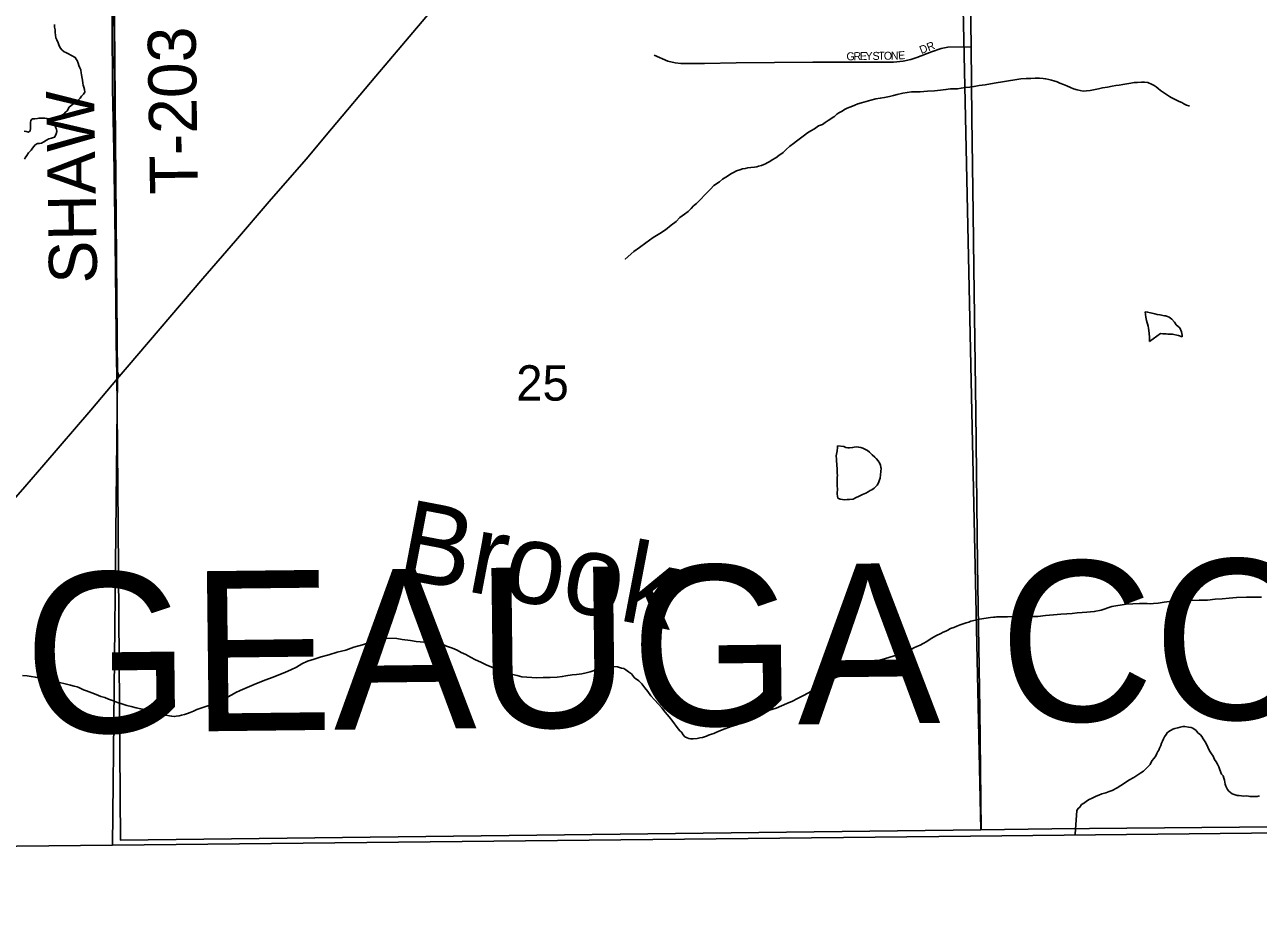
# Model space of a CAD drawing. Extents: x -10.1 to 68, y -9.5 to 29.2.
# Drawn here: x 6.404 to 7.864, y 16.795 to 17.837 of the extents above; entities that cross this region are included whole.
import ezdxf

# ---------------------------------------------------------------- set-up
doc = ezdxf.new("R2010")
doc.units = 0
for name, color, linetype in [('GM_X_Adjacent_County', 7, 'Continuous'), ('GM_X_Adjacent_County_Text', 7, 'Continuous'), ('GM_X_County_Road', 7, 'Continuous'), ('GM_X_Minor_Lake', 7, 'Continuous'), ('GM_X_Minor_River', 7, 'Continuous'), ('GM_X_Minor_River_Text', 7, 'Continuous'), ('GM_X_Section', 7, 'Continuous'), ('GM_X_Section_Text', 7, 'Continuous'), ('GM_X_Township', 7, 'Continuous'), ('GM_X_Township_Road', 7, 'Continuous'), ('GM_X_Township_Road_Text', 7, 'Continuous'), ('GM_X_Township_Subdivision', 7, 'Continuous'), ('GM_X_Township_Subdivision_Text', 7, 'Continuous')]:
    doc.layers.add(name, color=color, linetype=linetype)

msp = doc.modelspace()

# ---------------------------------------------------------------- linework, layer by layer
at = {"layer": 'GM_X_Adjacent_County'}
msp.add_lwpolyline([(8.9, 16.8967), (8.5023, 16.8904), (7.9665, 16.8821), (7.5233, 16.8774), (6.5083, 16.8667), (6.2435, 16.8638), (4.8206, 16.8372), (4.1632, 16.8285), (3.6875, 16.8223), (2.8045, 16.808), (2.1, 16.7954)], dxfattribs=at)
at = {"layer": 'GM_X_County_Road'}
msp.add_lwpolyline([(7.495, 19.6038), (7.4962, 19.5624), (7.4978, 19.473), (7.501, 19.2631), (7.5047, 19.0477), (7.5089, 18.8338), (7.5108, 18.7383), (7.5113, 18.6856), (7.513, 18.6303), (7.5141, 18.5902), (7.5161, 18.4613), (7.5177, 18.3096), (7.5197, 18.1709), (7.5217, 17.9835), (7.5233, 17.8668), (7.524, 17.8111), (7.5251, 17.7267), (7.5267, 17.614), (7.5273, 17.5492), (7.5298, 17.379), (7.5318, 17.1984), (7.5343, 17.0271), (7.5359, 16.8846)], dxfattribs=at)
at = {"layer": 'GM_X_Minor_Lake'}
for points in [[(6.4042, 17.6779), (6.4049, 17.6798), (6.4068, 17.6825), (6.409, 17.6856), (6.4119, 17.6887), (6.4138, 17.6911), (6.4153, 17.693), (6.4168, 17.6949), (6.4194, 17.6965), (6.422, 17.6966), (6.4243, 17.697), (6.4269, 17.6986), (6.4303, 17.7006), (6.4329, 17.7022), (6.436, 17.703), (6.4398, 17.7042), (6.4408, 17.7061), (6.4416, 17.7081), (6.4423, 17.7107), (6.4422, 17.7134), (6.4414, 17.7153), (6.4406, 17.7175), (6.4394, 17.7202), (6.4374, 17.7232), (6.4355, 17.7243), (6.4328, 17.7254), (6.4305, 17.7261), (6.4282, 17.7264), (6.4255, 17.7267), (6.4236, 17.7267), (6.4214, 17.7266), (6.4195, 17.7262), (6.4164, 17.7257), (6.4134, 17.7257), (6.4115, 17.7237), (6.4112, 17.7214), (6.4113, 17.7188), (6.4113, 17.7165), (6.4114, 17.7142), (6.4107, 17.7115), (6.4088, 17.71), (6.4061, 17.7107), (6.4038, 17.711)], [(7.7529, 17.4928), (7.7474, 17.494), (7.7443, 17.4943), (7.7413, 17.495), (7.7382, 17.4957), (7.7363, 17.4964), (7.7328, 17.4971), (7.7302, 17.4974), (7.7306, 17.4943), (7.7307, 17.4913), (7.7311, 17.489), (7.7315, 17.4871), (7.7336, 17.4807), (7.734, 17.4781), (7.7345, 17.4754), (7.7349, 17.472), (7.735, 17.4674), (7.7351, 17.4625)], [(7.7351, 17.4625), (7.7482, 17.4719), (7.7509, 17.4716), (7.7547, 17.4713), (7.757, 17.471), (7.7597, 17.471), (7.762, 17.4711), (7.7696, 17.4694), (7.7738, 17.4679), (7.7738, 17.4698), (7.7729, 17.474), (7.7709, 17.4785), (7.769, 17.48), (7.7667, 17.4822), (7.7647, 17.4852), (7.7616, 17.4886), (7.7585, 17.4912), (7.7565, 17.4919), (7.7539, 17.4926), (7.7529, 17.4928)], [(7.3659, 17.3388), (7.3659, 17.3369), (7.3656, 17.3331), (7.3646, 17.3273), (7.3647, 17.3232), (7.3653, 17.3148), (7.3657, 17.3129), (7.3657, 17.3106), (7.3658, 17.3083), (7.3658, 17.3064), (7.3659, 17.3042), (7.3656, 17.3015), (7.3656, 17.2984), (7.3657, 17.2962), (7.3657, 17.2943), (7.3658, 17.2908), (7.3659, 17.2886), (7.3659, 17.2863), (7.3656, 17.2844), (7.3656, 17.2817), (7.3661, 17.2794), (7.3665, 17.2772), (7.3692, 17.2757), (7.3719, 17.2754), (7.3745, 17.2751), (7.3776, 17.2755), (7.3802, 17.2756), (7.3844, 17.276), (7.3874, 17.2773), (7.3916, 17.2793), (7.3957, 17.2812), (7.3995, 17.2829), (7.4025, 17.2844), (7.4047, 17.286), (7.4066, 17.2868), (7.4096, 17.2888), (7.413, 17.2923), (7.4144, 17.295), (7.4158, 17.2988), (7.4166, 17.3007), (7.4175, 17.3127)], [(7.4175, 17.3127), (7.4174, 17.3133), (7.417, 17.316), (7.4162, 17.3182), (7.4142, 17.3212), (7.4119, 17.3239), (7.4103, 17.3257), (7.4072, 17.3283), (7.4037, 17.3313), (7.4014, 17.3335), (7.3983, 17.335), (7.396, 17.3361), (7.3937, 17.3368), (7.391, 17.3375), (7.3883, 17.3378), (7.3857, 17.3373), (7.3838, 17.3369), (7.3804, 17.3365), (7.3785, 17.3364), (7.3758, 17.3371), (7.3735, 17.3382), (7.3659, 17.3388)]]:
    msp.add_lwpolyline(points, dxfattribs=at)
at = {"layer": 'GM_X_Minor_River'}
for points in [[(6.4374, 17.7232), (6.4509, 17.7315), (6.4528, 17.7338), (6.4546, 17.7354), (6.4572, 17.7396), (6.4594, 17.7416), (6.4624, 17.7439), (6.4643, 17.7455), (6.4669, 17.7471), (6.4699, 17.7502), (6.4717, 17.7525), (6.474, 17.7548), (6.4754, 17.7572), (6.475, 17.7606), (6.4742, 17.7632), (6.4737, 17.7655), (6.4733, 17.7681), (6.4728, 17.7716), (6.472, 17.7753), (6.4715, 17.778), (6.4711, 17.7799), (6.4707, 17.7837), (6.4695, 17.7859), (6.4686, 17.789), (6.4678, 17.7916), (6.4666, 17.7946), (6.4654, 17.7965), (6.4642, 17.7984), (6.4554, 17.8031), (6.4531, 17.8042), (6.4511, 17.8049), (6.4484, 17.8075), (6.4469, 17.8094), (6.4453, 17.812), (6.444, 17.8158), (6.4424, 17.8192), (6.4413, 17.8214), (6.4408, 17.8249), (6.4403, 17.8279), (6.4403, 17.8309), (6.4398, 17.834), (6.4397, 17.8374)], [(7.115, 17.5599), (7.1251, 17.5688), (7.115, 17.5599), (7.1251, 17.5688), (7.1318, 17.5736), (7.1393, 17.5791), (7.1479, 17.5853), (7.1558, 17.5901), (7.1625, 17.5944), (7.1693, 17.5999), (7.1752, 17.6042), (7.1793, 17.6089), (7.1849, 17.6128), (7.1894, 17.616), (7.1928, 17.6195), (7.1957, 17.623), (7.1991, 17.6257), (7.2017, 17.628), (7.2047, 17.6312), (7.2084, 17.635), (7.2121, 17.6389), (7.2158, 17.6424), (7.2199, 17.6467), (7.2263, 17.6514), (7.23, 17.6542), (7.2338, 17.6569), (7.2372, 17.6589), (7.2398, 17.6605), (7.2428, 17.6621), (7.2465, 17.6641), (7.2503, 17.6653), (7.2537, 17.6665), (7.2568, 17.667), (7.2598, 17.6678), (7.2636, 17.6683), (7.2678, 17.6684), (7.2704, 17.6688), (7.2727, 17.6696), (7.2761, 17.6705), (7.2787, 17.6717), (7.281, 17.6725), (7.2829, 17.6737), (7.2859, 17.6752), (7.2889, 17.6772), (7.293, 17.6796), (7.2967, 17.6823), (7.3016, 17.6859), (7.3053, 17.6894), (7.3098, 17.6933), (7.3139, 17.6964), (7.3177, 17.6992), (7.327, 17.7066), (7.3304, 17.709), (7.3345, 17.7114), (7.339, 17.7141), (7.3435, 17.7173), (7.3484, 17.7189), (7.3514, 17.7213), (7.3548, 17.7236), (7.3581, 17.7256), (7.3608, 17.7276), (7.3626, 17.7284), (7.3653, 17.7311), (7.3675, 17.7327), (7.3698, 17.7339), (7.3716, 17.735), (7.3743, 17.7366), (7.3776, 17.7382), (7.3807, 17.7394), (7.3837, 17.7406), (7.3867, 17.7419), (7.3901, 17.7434), (7.3946, 17.7447), (7.3999, 17.7463), (7.4056, 17.748), (7.4113, 17.7493), (7.4166, 17.7501), (7.4215, 17.751), (7.4275, 17.7523), (7.4321, 17.7535), (7.4366, 17.7544), (7.4434, 17.7561), (7.4537, 17.7575), (7.464, 17.7577), (7.4727, 17.7583), (7.4807, 17.7588), (7.4879, 17.7598), (7.4943, 17.7603), (7.4996, 17.7612), (7.5042, 17.7613), (7.508, 17.7614), (7.5125, 17.7622), (7.5175, 17.7627), (7.5224, 17.7632), (7.5277, 17.7641), (7.5338, 17.765), (7.5406, 17.7659), (7.5471, 17.7672), (7.5539, 17.7685), (7.5611, 17.7694), (7.5831, 17.773)], [(7.5831, 17.773), (7.5892, 17.7735), (7.5949, 17.7736), (7.5998, 17.7737), (7.6051, 17.7738), (7.6093, 17.7736), (7.6124, 17.7729), (7.6162, 17.7722), (7.6193, 17.7715), (7.6219, 17.7708), (7.6258, 17.7694), (7.6292, 17.7679), (7.6335, 17.7665), (7.6373, 17.7647), (7.6415, 17.7629), (7.6454, 17.7611), (7.6496, 17.76), (7.653, 17.7593), (7.6565, 17.7586), (7.6606, 17.7587), (7.6648, 17.7592), (7.669, 17.7601), (7.6747, 17.7613), (7.6796, 17.7626), (7.6853, 17.7631), (7.691, 17.7644), (7.6955, 17.7652), (7.6993, 17.7657), (7.7035, 17.7662), (7.7084, 17.7671), (7.7129, 17.7679), (7.7171, 17.7688), (7.7209, 17.7689), (7.7255, 17.7693), (7.7293, 17.7691), (7.7331, 17.7688), (7.7385, 17.7662), (7.7408, 17.7651), (7.7431, 17.7637), (7.7454, 17.7618), (7.7481, 17.7592), (7.7516, 17.757), (7.7539, 17.7552), (7.7566, 17.7537), (7.759, 17.7522), (7.7609, 17.7511), (7.7701, 17.7464), (7.7736, 17.7449), (7.7759, 17.7435), (7.779, 17.742), (7.7817, 17.7413), (7.7824, 17.741)], [(7.4562, 17.1), (7.4599, 17.1016), (7.4637, 17.1032), (7.4675, 17.1052), (7.4716, 17.1076), (7.4757, 17.1103), (7.4795, 17.1127), (7.4832, 17.1147), (7.4881, 17.1171), (7.4911, 17.1187), (7.4941, 17.1199), (7.4964, 17.1211), (7.4998, 17.1227), (7.5036, 17.1239), (7.5073, 17.1255), (7.5111, 17.1271), (7.5149, 17.1283), (7.5183, 17.1295), (7.5213, 17.1304), (7.5239, 17.1316), (7.5292, 17.1328), (7.5341, 17.1341), (7.547, 17.1359), (7.5505, 17.1364), (7.5524, 17.1364), (7.5543, 17.1365), (7.5569, 17.1365), (7.5611, 17.1366), (7.5672, 17.1368), (7.5767, 17.137), (7.5851, 17.1368), (7.5942, 17.137), (7.6029, 17.1372), (7.6121, 17.1382), (7.6215, 17.1391), (7.6303, 17.1397), (7.6375, 17.1403), (7.6436, 17.1408), (7.6496, 17.1413), (7.6553, 17.1418), (7.661, 17.1423), (7.6698, 17.1429), (7.6781, 17.1446), (7.6906, 17.1491), (7.7076, 17.1517), (7.7232, 17.1525), (7.7323, 17.1523), (7.7358, 17.152), (7.74, 17.1525), (7.7453, 17.153), (7.7525, 17.1539), (7.7616, 17.1553), (7.7726, 17.1559), (7.7836, 17.1561), (7.7939, 17.1564), (7.8038, 17.1566), (7.8129, 17.1576), (7.8212, 17.1581), (7.8296, 17.1587), (7.838, 17.1597), (7.8501, 17.1599), (7.8589, 17.1601), (7.8676, 17.1599)], [(6.4121, 17.0662), (6.4171, 17.0652), (6.4224, 17.0642), (6.4308, 17.0629), (6.4381, 17.0607), (6.4454, 17.059), (6.4523, 17.0573), (6.4584, 17.0559), (6.463, 17.0545), (6.4664, 17.0538), (6.4683, 17.0531), (6.4707, 17.052), (6.4741, 17.0505), (6.4776, 17.0491), (6.4837, 17.0469), (6.4891, 17.0448), (6.4945, 17.0426), (6.4994, 17.0412), (6.5037, 17.0394), (6.5083, 17.0376), (6.514, 17.0355), (6.5194, 17.0337), (6.5251, 17.0319), (6.5305, 17.0305), (6.5362, 17.0291), (6.5416, 17.0277), (6.5492, 17.0264), (6.5661, 17.0218), (6.5714, 17.0204), (6.5756, 17.0197), (6.5783, 17.019), (6.5814, 17.0187), (6.5836, 17.0192), (6.5871, 17.0196), (6.5901, 17.0205), (6.5935, 17.0213), (6.5969, 17.0225), (6.6003, 17.0237), (6.6041, 17.0253), (6.6082, 17.027), (6.6127, 17.0286), (6.6176, 17.0302), (6.6222, 17.0318), (6.6267, 17.0335), (6.632, 17.0366), (6.6395, 17.0391), (6.6444, 17.0415), (6.6493, 17.0443), (6.6542, 17.047), (6.6594, 17.0494), (6.6647, 17.0518), (6.6704, 17.0543), (6.676, 17.0567), (6.6824, 17.0595), (6.6896, 17.0623), (6.6971, 17.0648), (6.7062, 17.0684), (6.713, 17.0712), (6.7194, 17.074), (6.7258, 17.0772), (6.7321, 17.0812), (6.7389, 17.0844), (6.7469, 17.0868), (6.7552, 17.0893), (6.7642, 17.0918), (6.7741, 17.0947), (6.7843, 17.0972), (6.7937, 17.1008), (6.8039, 17.1034), (6.81, 17.1054), (6.8149, 17.107), (6.819, 17.1086), (6.8236, 17.1095), (6.8277, 17.1107), (6.8315, 17.1116), (6.8445, 17.1111), (6.851, 17.1098), (6.8609, 17.1085), (6.8674, 17.1075), (6.8723, 17.1072), (6.8761, 17.1069), (6.8788, 17.107), (6.8811, 17.107), (6.8834, 17.1071), (6.886, 17.1068), (6.8902, 17.1065), (6.894, 17.1058), (6.8983, 17.1044), (6.9033, 17.1018), (6.9105, 17.0997), (6.9159, 17.0972), (6.9209, 17.0946), (6.9263, 17.0921), (6.9317, 17.0888), (6.9379, 17.0859), (6.944, 17.083), (6.9502, 17.0801), (6.9571, 17.0772), (6.9636, 17.0743), (6.9698, 17.0725), (6.9767, 17.0704)], [(6.9767, 17.0704), (6.9816, 17.0686), (6.987, 17.0672), (6.9927, 17.0658), (6.9985, 17.0652), (7.0042, 17.0649), (7.0103, 17.0647), (7.0179, 17.0649), (7.0262, 17.0651), (7.0342, 17.0652), (7.0403, 17.0661), (7.0448, 17.067), (7.0521, 17.0679), (7.0574, 17.0684), (7.0634, 17.0693), (7.0687, 17.0706), (7.0733, 17.0718), (7.0771, 17.0727), (7.0808, 17.0739), (7.0839, 17.0747), (7.0861, 17.0756), (7.0884, 17.076), (7.0907, 17.0768), (7.0941, 17.0776), (7.0971, 17.0781), (7.1059, 17.0775), (7.1082, 17.0768), (7.1105, 17.0761), (7.1131, 17.0754), (7.1158, 17.074), (7.1189, 17.0717), (7.1224, 17.0692), (7.1259, 17.0647), (7.131, 17.061), (7.1345, 17.0573), (7.138, 17.0528), (7.1415, 17.0483), (7.1451, 17.0434), (7.1494, 17.0386), (7.1541, 17.0333), (7.1583, 17.0289), (7.1623, 17.024), (7.167, 17.0184), (7.1713, 17.0128), (7.1764, 17.0057), (7.1795, 17.002), (7.1814, 17.0001), (7.1834, 16.9971), (7.1854, 16.9949), (7.1881, 16.9934), (7.19, 16.9927), (7.1923, 16.9924), (7.1953, 16.9924), (7.1999, 16.9929), (7.2033, 16.9934), (7.2063, 16.9938), (7.2086, 16.9946), (7.2109, 16.9955), (7.2135, 16.9967), (7.2169, 16.9979), (7.2199, 16.9987), (7.2222, 16.9999), (7.2248, 17.0011), (7.2278, 17.0023), (7.2327, 17.0043), (7.2369, 17.0056), (7.2414, 17.0072), (7.2456, 17.0084), (7.249, 17.0096), (7.2535, 17.0113), (7.258, 17.0133), (7.2629, 17.0157), (7.2795, 17.0229), (7.2855, 17.0261), (7.2934, 17.0285), (7.2998, 17.0313), (7.3062, 17.0342), (7.3126, 17.037), (7.3187, 17.0401), (7.325, 17.0433), (7.3318, 17.0469), (7.3382, 17.0509), (7.3446, 17.0544), (7.3513, 17.0588), (7.3585, 17.0624), (7.3668, 17.066), (7.3724, 17.0684), (7.3777, 17.0708), (7.383, 17.0728), (7.3883, 17.0748), (7.3935, 17.0769), (7.3996, 17.0789), (7.406, 17.0813), (7.4135, 17.0845), (7.423, 17.0874), (7.432, 17.0903), (7.4396, 17.0927), (7.4464, 17.0944), (7.4494, 17.096), (7.4524, 17.0976), (7.4562, 17.1)], [(6.4018, 17.0671), (6.4075, 17.0669), (6.4121, 17.0662)], [(7.6472, 16.8798), (7.6493, 16.9076), (7.6508, 16.91), (7.6526, 16.9115), (7.6548, 16.9146), (7.6582, 16.9166), (7.6608, 16.9186), (7.6638, 16.9205), (7.6672, 16.9221), (7.6695, 16.9233), (7.6721, 16.9245), (7.6751, 16.9257), (7.6789, 16.9273), (7.6834, 16.9286), (7.6876, 16.9302), (7.691, 16.9314), (7.697, 16.9346), (7.7011, 16.937), (7.7056, 16.9401), (7.7109, 16.9433), (7.7165, 16.9468), (7.7214, 16.9496), (7.7251, 16.952), (7.7281, 16.9543), (7.7311, 16.9571), (7.7337, 16.9598), (7.7359, 16.9621), (7.7381, 16.9664), (7.7407, 16.9695), (7.7426, 16.9722), (7.744, 16.9749), (7.7451, 16.9772), (7.7462, 16.9791), (7.7469, 16.9814), (7.7484, 16.9845), (7.7494, 16.9872), (7.7505, 16.9895), (7.7516, 16.9922), (7.7531, 16.9949), (7.7549, 16.9976), (7.756, 16.9995), (7.7579, 17.0011), (7.7628, 17.0038), (7.765, 17.0046), (7.7688, 17.0055), (7.7715, 17.0063), (7.7745, 17.0068), (7.7771, 17.0068), (7.7813, 17.0062), (7.7844, 17.0058), (7.7863, 17.0051), (7.7902, 17.0022), (7.7925, 16.9996), (7.7953, 16.997), (7.7972, 16.9951), (7.7988, 16.9925), (7.8011, 16.9887), (7.8027, 16.9861), (7.8043, 16.9827), (7.8063, 16.9782), (7.8087, 16.9748), (7.8103, 16.9718), (7.8119, 16.968), (7.8139, 16.965), (7.8155, 16.9624), (7.817, 16.9594), (7.8183, 16.9556), (7.8203, 16.9507), (7.8222, 16.9485), (7.8231, 16.9458), (7.8239, 16.9436), (7.8243, 16.9413), (7.8247, 16.9387), (7.8256, 16.9364), (7.8275, 16.9326), (7.8291, 16.9304), (7.8311, 16.9289), (7.833, 16.9274), (7.8364, 16.926), (7.8387, 16.9253), (7.8414, 16.9253), (7.8441, 16.925), (7.8468, 16.9247), (7.8494, 16.9248), (7.8521, 16.9244), (7.854, 16.9241), (7.8567, 16.9242), (7.8589, 16.9242), (7.8627, 16.9243), (7.8654, 16.9251)]]:
    msp.add_lwpolyline(points, dxfattribs=at)
at = {"layer": 'GM_X_Section'}
for points in [[(8.4834, 18.0059), (8.5076, 16.8938), (7.6195, 16.8859), (7.5357, 16.8848), (7.5119, 17.9844)], [(7.5119, 17.9844), (7.5357, 16.8848), (6.5178, 16.8724), (6.515, 17.2445), (6.5119, 17.6092), (6.5089, 17.9612)]]:
    msp.add_lwpolyline(points, close=True, dxfattribs=at)
at = {"layer": 'GM_X_Township'}
msp.add_lwpolyline([(6.49, 20.9), (6.4976, 19.3842), (6.5141, 17.4202), (6.5083, 16.8667), (7.5233, 16.8774), (7.9665, 16.8821), (8.5023, 16.8904), (8.9, 16.8967)], dxfattribs=at)
at = {"layer": 'GM_X_Township_Road'}
for points in [[(6.516, 17.421), (6.514, 17.4263), (6.5131, 17.4329), (6.5113, 17.5817), (6.5097, 17.6881), (6.5081, 17.7615), (6.5079, 17.838), (6.507, 17.9485), (6.5041, 18.126), (6.5039, 18.172), (6.5032, 18.3103), (6.5025, 18.6855)], [(6.9292, 17.9056), (6.8506, 17.8125), (6.8199, 17.7761), (6.7673, 17.714), (6.7375, 17.678), (6.6935, 17.628), (6.6538, 17.5815), (6.615, 17.5368), (6.5256, 17.432), (6.516, 17.421)], [(6.516, 17.421), (6.5141, 17.4188), (6.4825, 17.3813), (6.4269, 17.3164), (6.4044, 17.2906), (6.3555, 17.2349), (6.3102, 17.1786), (6.2823, 17.1438), (6.2763, 17.1355), (6.2711, 17.1259), (6.268, 17.1182), (6.265, 17.1077), (6.263, 17.0951), (6.2597, 17.0572), (6.2531, 16.9367), (6.2516, 16.888), (6.25, 16.8711)]]:
    msp.add_lwpolyline(points, dxfattribs=at)
at = {"layer": 'GM_X_Township_Subdivision'}
msp.add_lwpolyline([(7.524, 17.8111), (7.4966, 17.8104), (7.4885, 17.8089), (7.4771, 17.805), (7.46, 17.7983), (7.4526, 17.7958), (7.4436, 17.7938), (7.4324, 17.7929), (7.4115, 17.7929), (7.3369, 17.7927), (7.2461, 17.7919), (7.2088, 17.7913), (7.1897, 17.7911), (7.1807, 17.7913), (7.1738, 17.7921), (7.1654, 17.794), (7.1492, 17.8009)], dxfattribs=at)

# ---------------------------------------------------------------- texts
at = {"layer": 'GM_X_Adjacent_County_Text'}
msp.add_text('GEAUGA COUNTY', height=0.189394, rotation=0.6619, dxfattribs=at).set_placement((6.4044, 16.9988))
at = {"layer": 'GM_X_Minor_River_Text'}
msp.add_text('Brook', height=0.09475, rotation=349.2053, dxfattribs=at).set_placement((6.8424, 17.1831))
at = {"layer": 'GM_X_Section_Text'}
msp.add_text('25', height=0.04186, rotation=0, dxfattribs=at).set_placement((6.9859, 17.3924))
at = {"layer": 'GM_X_Township_Road_Text'}
for s, rotation, p in [('T-203', 90.846, (6.6095, 17.6367)), ('SHAW', 90.9362, (6.4902, 17.5313))]:
    msp.add_text(s, height=0.05682, rotation=rotation, dxfattribs=at).set_placement(p)
at = {"layer": 'GM_X_Township_Subdivision_Text'}
for s, rotation, p in [('DR', 21.2552, (7.4652, 17.8023)), ('G', 0.9181, (7.3767, 17.7949)), ('R', 0.9558, (7.385, 17.7951)), ('E', 0.9289, (7.3925, 17.7952)), ('Y', 0.9279, (7.3992, 17.7953)), ('S', 0.9364, (7.4075, 17.7954)), ('T', 0.9289, (7.4142, 17.7955)), ('O', 0.9279, (7.4209, 17.7956)), ('N', 0.9504, (7.4292, 17.7958)), ('E', 4.2185, (7.4381, 17.7959))]:
    msp.add_text(s, height=0.00947, rotation=rotation, dxfattribs=at).set_placement(p)

doc.saveas('drawing.dxf')
